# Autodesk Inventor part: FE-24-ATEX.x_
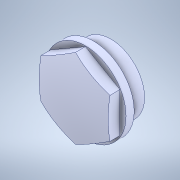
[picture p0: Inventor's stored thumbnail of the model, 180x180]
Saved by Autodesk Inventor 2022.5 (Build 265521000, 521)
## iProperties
Created: 2023-04
Part Number: FE-24-ATEX.x_
Material: Generic
Document SubType Name: Modeling
Designer: ImaoCorp
Density: 1 g/cm^3
Appearance: Default
Sending System: SOLIDWORKS 2021-2021301
MC: AMD64
MC_MODEL: Intel64 Family 6 Model 60 Stepping 3, GenuineIntel
OS: Windows_NT
FRU: Parasolid Version 32.1, build 255,  1- 1-2021
FORMAT: text
GUISE: transmit
KEY: fe-24-atex
FILE: fe-24-atex.x_t
DATE: Tue Apr  4 17:13:00 2023
Author: ImaoCorp
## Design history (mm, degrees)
feature "Base1"
node "ソリッド1"
